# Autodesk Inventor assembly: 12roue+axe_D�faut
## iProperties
Created: 2011-01
Part Number: 12roue+axe_D�faut
Document SubType Name: Assembly
Designer: eric
Mass: 62.4241 g
Surface Area: 248.334 cm^2
Volume: 62.4241 cm^3
Density: 1 g/cm^3
Author: eric
